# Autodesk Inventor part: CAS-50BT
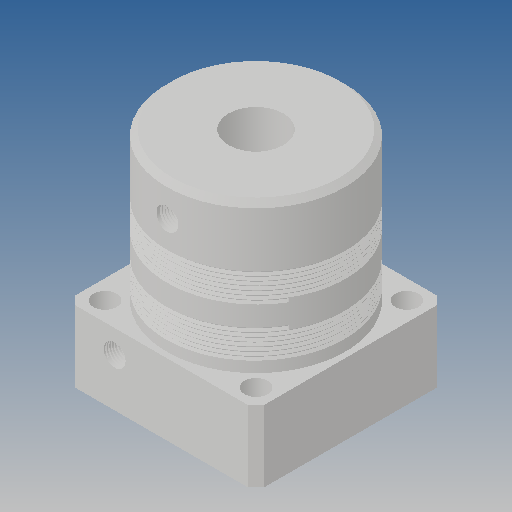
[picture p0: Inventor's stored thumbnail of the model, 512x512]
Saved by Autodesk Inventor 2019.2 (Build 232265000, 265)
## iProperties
Created: 2009-09
Part Number: CAS-50BT
Material: Ogólny
Document SubType Name: Modeling
Designer: CADENGINEERING4
Density: 1 g/cm^3
Appearance: Domyślna
Author: CADENGINEERING4
Revision Number: 1LAST_VERSION
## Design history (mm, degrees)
feature "Baza1"
node "Bryła1"
